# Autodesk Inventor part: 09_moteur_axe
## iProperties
Shininess: 41.0
Length Units: 11269
Angle Units: 11279
Time Units: 11290
Mass Units: 11283
Length Display Precision: 3
Angle Display Precision: 2
Compacted: True
Created: 2002-11
Part Number: 09_moteur_axe
Material: Par défaut
Document SubType Name: Modélisation
Designer: FIEVET
Density: 0.0
Volumn: 0.0
Area: 0.0
PropertySet Name: Model Information
Control State: 0
Master: False
Checked Out: False
Author: FIEVET
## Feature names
1. Révolution1 [Revolution]
2. Extrusion1
3. Réseau circulaire1 [Circular Pattern]
